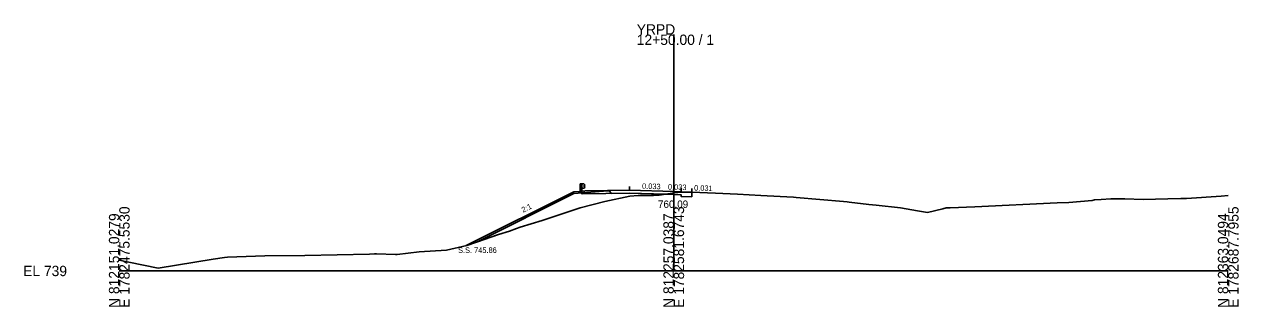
# Model space of a CAD drawing. Extents: x -26 to 1403, y -10 to 9544.
# Drawn here: x -25.7 to 302.8, y 2490.3 to 2566.8 of the extents above; entities that cross this region are included whole.
import ezdxf

# ---------------------------------------------------------------- set-up
doc = ezdxf.new("R2010")
doc.units = 0
for name, color, linetype in [('Exist Cross Section Cell', 7, 'Continuous'), ('Exist XS Center Line Elevation Label', 7, 'Continuous'), ('Exist XS Ground Line', 7, 'Continuous'), ('Prop XS Dump Level', 7, 'Continuous'), ('Prop XS Earthwork Shape', 7, 'Continuous'), ('Prop XS EOT Tick Mark', 7, 'Continuous'), ('Prop XS Finish Grade', 7, 'Continuous'), ('Prop XS Finish Grade Earthwork', 7, 'Continuous'), ('Prop XS Finish Grade Paved Shoulder', 7, 'Continuous'), ('Prop XS Finish Grade Pavement', 7, 'Continuous'), ('Prop XS Guardrail', 7, 'Continuous'), ('Prop XS Pvmt Edge Slope', 7, 'Continuous'), ('Prop XS SE Text', 7, 'Continuous'), ('Prop XS Side Slope Text', 7, 'Continuous'), ('Prop XS SS Elevation Text', 7, 'Continuous'), ('Prop XS Subgrade Earthwork', 7, 'Continuous')]:
    doc.layers.add(name, color=color, linetype=linetype)

msp = doc.modelspace()

# ---------------------------------------------------------------- linework, layer by layer
at = {"layer": 'Exist Cross Section Cell'}
for p, q in [((150, 2500), (150, 2564.02)), ((0, 2500), (150, 2500)), ((150, 2500), (300, 2500))]:
    msp.add_line(p, q, dxfattribs=at)
at = {"layer": 'Exist XS Ground Line'}
for p, q in [((131.32, 2518.78), (138.11, 2520.25)), ((138.11, 2520.25), (140.35, 2520.4)), ((140.35, 2520.4), (144.51, 2520.48)), ((144.51, 2520.48), (146.1, 2520.56)), ((146.1, 2520.56), (150.25, 2521.12)), ((150.25, 2521.12), (151.07, 2521.25)), ((151.07, 2521.25), (154.94, 2521.34)), ((154.94, 2521.34), (161.32, 2521.07)), ((161.32, 2521.07), (167.22, 2520.82)), ((167.22, 2520.82), (173.59, 2520.48)), ((173.59, 2520.48), (178.8, 2520.21)), ((178.8, 2520.21), (182.37, 2519.99)), ((182.37, 2519.99), (183.16, 2519.92)), ((183.16, 2519.92), (195.94, 2518.82)), ((288.75, 2519.61), (298.1, 2520.27)), ((298.1, 2520.27), (300, 2520.43)), ((114.38, 2513.66), (124.7, 2517.1)), ((124.7, 2517.1), (131.32, 2518.78)), ((195.94, 2518.82), (196.89, 2518.72)), ((196.89, 2518.72), (197.47, 2518.66)), ((197.47, 2518.66), (202.75, 2518.04)), ((202.75, 2518.04), (204.8, 2517.81)), ((204.8, 2517.81), (211.36, 2517.09)), ((211.36, 2517.09), (215.92, 2516.3)), ((218.63, 2515.87), (222.77, 2516.87)), ((222.77, 2516.87), (223.7, 2517.08)), ((223.7, 2517.08), (224.76, 2517.11)), ((224.76, 2517.11), (231.48, 2517.41)), ((231.48, 2517.41), (253.7, 2518.46)), ((253.7, 2518.46), (256.88, 2518.53)), ((256.88, 2518.53), (263.24, 2519.06)), ((263.24, 2519.06), (263.8, 2519.31)), ((263.8, 2519.31), (265.6, 2519.37)), ((265.6, 2519.37), (268.21, 2519.56)), ((268.21, 2519.56), (272, 2519.53)), ((272, 2519.53), (276.98, 2519.37)), ((276.98, 2519.37), (283.71, 2519.57)), ((283.71, 2519.57), (287.21, 2519.64)), ((287.21, 2519.64), (288.75, 2519.61)), ((108.45, 2511.83), (114.38, 2513.66)), ((215.92, 2516.3), (218.63, 2515.87)), ((102.58, 2509.85), (105.55, 2510.82)), ((105.55, 2510.82), (107.49, 2511.54)), ((107.49, 2511.54), (108.45, 2511.83)), ((88.52, 2505.66), (94.04, 2506.89)), ((94.04, 2506.89), (102.58, 2509.85)), ((25.4, 2503.17), (28.44, 2503.66)), ((28.44, 2503.66), (29.31, 2503.7)), ((29.31, 2503.7), (39.37, 2504.11)), ((39.37, 2504.11), (50.22, 2504.19)), ((50.22, 2504.19), (67.72, 2504.59)), ((67.72, 2504.59), (69.07, 2504.61)), ((69.07, 2504.61), (69.62, 2504.64)), ((69.62, 2504.64), (74.72, 2504.5)), ((74.72, 2504.5), (75.14, 2504.5)), ((75.14, 2504.5), (81.1, 2505.2)), ((81.1, 2505.2), (88.52, 2505.66)), ((0, 2502.92), (2.62, 2502.41)), ((2.62, 2502.41), (10.5, 2500.78)), ((10.5, 2500.78), (25.4, 2503.17))]:
    msp.add_line(p, q, dxfattribs=at)
at = {"layer": 'Prop XS Dump Level'}
for p, q in [((138, 2521.9), (150, 2521.5)), ((150, 2521.5), (152, 2521.43))]:
    msp.add_line(p, q, dxfattribs=at)
at = {"layer": 'Prop XS Earthwork Shape'}
for points in [[(133.19, 2521.01), (132.5, 2521.7), (131, 2521.58), (123, 2520.94), (96.88, 2507.88), (102.58, 2509.85), (105.55, 2510.82), (107.49, 2511.54), (108.45, 2511.83), (114.38, 2513.66), (124.7, 2517.1), (131.32, 2518.78), (138.11, 2520.25), (140.35, 2520.4), (144.51, 2520.48), (146.1, 2520.56), (147.75, 2520.78), (137.99, 2521.11)], [(154.93, 2520.09), (154.93, 2521.34), (151.07, 2521.25), (150.25, 2521.12), (147.75, 2520.78), (149.97, 2520.71), (152, 2520.64), (152, 2520.18)]]:
    msp.add_lwpolyline(points, close=True, dxfattribs=at)
at = {"layer": 'Prop XS EOT Tick Mark'}
for p, q in [((138, 2521.9), (138, 2522.9)), ((152, 2521.43), (152, 2522.43)), ((154.93, 2521.34), (154.93, 2522.34))]:
    msp.add_line(p, q, dxfattribs=at)
at = {"layer": 'Prop XS Finish Grade'}
msp.add_line((126, 2521.66), (124.5, 2521.54), dxfattribs=at)
at = {"layer": 'Prop XS Finish Grade Earthwork'}
for q in [(93.88, 2506.86), (124.5, 2521.54)]:
    msp.add_line((123, 2521.42), q, dxfattribs=at)
at = {"layer": 'Prop XS Finish Grade Paved Shoulder'}
for p, q in [((138, 2521.9), (126, 2521.66)), ((152, 2521.43), (154.93, 2521.34))]:
    msp.add_line(p, q, dxfattribs=at)
at = {"layer": 'Prop XS Finish Grade Pavement'}
for p, q in [((138, 2521.9), (150, 2521.5)), ((150, 2521.5), (152, 2521.43))]:
    msp.add_line(p, q, dxfattribs=at)
at = {"layer": 'Prop XS Guardrail'}
for p, q in [((124.68, 2523.57), (125.18, 2523.57)), ((124.68, 2521.07), (124.68, 2523.57)), ((125.18, 2523.57), (125.68, 2523.57)), ((125.18, 2523.57), (125.18, 2521.07)), ((125.68, 2523.57), (125.97, 2523.37)), ((125.97, 2523.25), (125.68, 2523.05)), ((125.97, 2523.37), (126, 2523.31)), ((126, 2523.31), (125.97, 2523.25)), ((125.68, 2522.44), (125.18, 2522.44)), ((125.68, 2523.05), (125.68, 2522.96)), ((125.68, 2522.96), (125.97, 2522.76)), ((125.97, 2522.64), (125.68, 2522.44)), ((125.97, 2522.76), (126, 2522.7)), ((126, 2522.7), (125.97, 2522.64))]:
    msp.add_line(p, q, dxfattribs=at)
at = {"layer": 'Prop XS Pvmt Edge Slope'}
msp.add_line((126, 2521.66), (125.19, 2520.85), dxfattribs=at)
at = {"layer": 'Prop XS Subgrade Earthwork'}
for p, q in [((125.19, 2520.85), (124.5, 2521.54)), ((137.99, 2521.11), (125.19, 2520.85)), ((137.99, 2521.11), (149.97, 2520.71)), ((149.97, 2520.71), (152, 2520.64)), ((152, 2520.18), (152, 2520.64)), ((152, 2520.18), (154.93, 2520.09)), ((154.93, 2520.09), (154.93, 2521.34))]:
    msp.add_line(p, q, dxfattribs=at)

# ---------------------------------------------------------------- texts
at = {"layer": 'Exist Cross Section Cell'}
for s, p in [('YRPD', (140, 2564.02)), ('12+50.00 / 1', (140, 2561.22)), ('EL 739', (-26, 2498.6))]:
    msp.add_text(s, height=2.8, dxfattribs=at).set_placement(p)
for s, p in [('E 1782475.5530', (2.8, 2490)), ('E 1782581.6743', (152.8, 2490)), ('E 1782687.7955', (302.8, 2490)), ('N 812151.0279', (0, 2490)), ('N 812257.0387', (150, 2490)), ('N 812363.0494', (300, 2490))]:
    msp.add_text(s, height=2.8, rotation=90, dxfattribs=at).set_placement(p)
at = {"layer": 'Exist XS Center Line Elevation Label'}
msp.add_text('760.09', height=2, dxfattribs=at).set_placement((145.73, 2517.09))
at = {"layer": 'Prop XS Dump Level'}
msp.add_text('Case4', height=0.04, dxfattribs=at).set_placement((126, 2521.14))
at = {"layer": 'Prop XS SE Text'}
for s, p in [('0.033', (141.41, 2522.28)), ('0.033', (148.41, 2522.05)), ('0.031', (155.49, 2521.78))]:
    msp.add_text(s, height=1.5, rotation=358.0908, dxfattribs=at).set_placement(p)
at = {"layer": 'Prop XS Side Slope Text'}
msp.add_text('2:1', height=1.5, rotation=26.5651, dxfattribs=at).set_placement((109.27, 2515.75))
at = {"layer": 'Prop XS SS Elevation Text'}
msp.add_text('S.S. 745.86', height=1.5, dxfattribs=at).set_placement((91.65, 2504.88))

doc.saveas('drawing.dxf')
